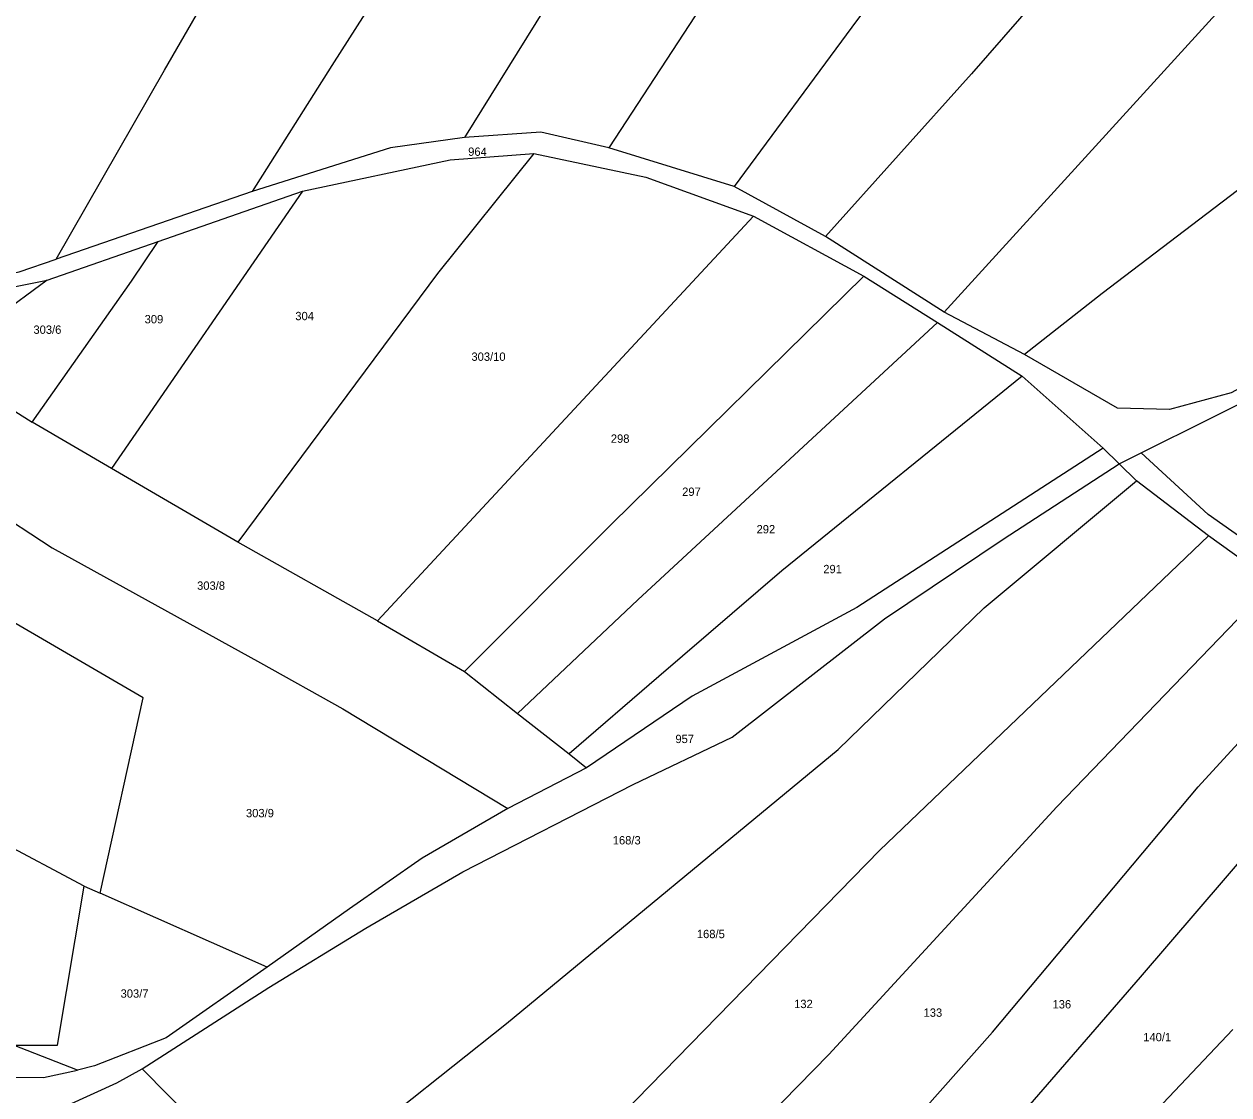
# Model space of a CAD drawing. Extents: x -7483133 to -743907, y -11317770 to -1129777.
# Drawn here: x -747616.9 to -747371.5, y -1130860.3 to -1130642.1 of the extents above; entities that cross this region are included whole.
import ezdxf

# ---------------------------------------------------------------- set-up
doc = ezdxf.new("R2010")
doc.units = 0
doc.layers.add('Hranice parcel', color=7, linetype='Continuous')
doc.layers.add('Parcelní čísla', color=7, linetype='Continuous')

msp = doc.modelspace()

# ---------------------------------------------------------------- linework, layer by layer
at = {"layer": 'Hranice parcel'}
for p, q in [((-747472.3, -1130675.24), (-747497.82, -1130667.33)), ((-747570.47, -1130676.24), (-747610.44, -1130690.04)), ((-747560.26, -1130676.14), (-747599.16, -1130732.71)), ((-747589.6, -1130686.4), (-747560.26, -1130676.14)), ((-747453.65, -1130685.38), (-747472.3, -1130675.24)), ((-747468.33, -1130681.23), (-747544.95, -1130763.72)), ((-747468.33, -1130681.23), (-747445.84, -1130693.47)), ((-747612.23, -1130694.29), (-747589.6, -1130686.4)), ((-747429.5, -1130700.84), (-747453.65, -1130685.38)), ((-747612.23, -1130694.29), (-747634.84, -1130710.99)), ((-747445.84, -1130693.47), (-747430.87, -1130702.94)), ((-747413.11, -1130709.47), (-747429.5, -1130700.84)), ((-747430.87, -1130702.94), (-747413.6, -1130713.86)), ((-747634.84, -1130710.99), (-747615.28, -1130723.21)), ((-747413.6, -1130713.86), (-747397.12, -1130728.52)), ((-747599.16, -1130732.71), (-747615.28, -1130723.21)), ((-747393.87, -1130731.74), (-747397.12, -1130728.52)), ((-747393.87, -1130731.74), (-747389.39, -1130729.51)), ((-747573.4, -1130747.66), (-747599.16, -1130732.71)), ((-747390.31, -1130735.18), (-747393.87, -1130731.74)), ((-747375.64, -1130746.37), (-747390.31, -1130735.18)), ((-747544.95, -1130763.72), (-747573.4, -1130747.66)), ((-747362.47, -1130755.89), (-747375.64, -1130746.37)), ((-747544.95, -1130763.72), (-747527.2, -1130774.05)), ((-747527.2, -1130774.05), (-747516.43, -1130782.61)), ((-747516.43, -1130782.61), (-747505.92, -1130790.81)), ((-747604.68, -1130817.79), (-747653.39, -1130792.09)), ((-747505.92, -1130790.81), (-747502.34, -1130793.69)), ((-747502.34, -1130793.69), (-747518.4, -1130801.96)), ((-747604.68, -1130817.79), (-747601.44, -1130819.19)), ((-747567.45, -1130834.27), (-747601.44, -1130819.19)), ((-747370.72, -1130846.96), (-747398.68, -1130876.61)), ((-747606.08, -1130855.29), (-747619.1, -1130850.16)), ((-747566.95, -1130881.22), (-747592.89, -1130855.02))]:
    msp.add_line(p, q, dxfattribs=at)
for points in [[(-747406.55, -1130442.05), (-747433, -1130473.56), (-747450.34, -1130497.42), (-747482.92, -1130542.77), (-747509.09, -1130578.6), (-747506.37, -1130580.24), (-747519.16, -1130597.89), (-747541.31, -1130630.19), (-747554.26, -1130650.56), (-747570.47, -1130676.24)], [(-747389.81, -1130462.1), (-747422.6, -1130502.65), (-747435.83, -1130522.84), (-747460.61, -1130558.7), (-747496.62, -1130615.91), (-747527.24, -1130665.21)], [(-747372.27, -1130486.53), (-747381.2, -1130496.17), (-747406.45, -1130532.04), (-747427.76, -1130561.72), (-747452.45, -1130598.71), (-747466.25, -1130619), (-747497.82, -1130667.33)], [(-747610.44, -1130690.04), (-747588.32, -1130651.53), (-747569.82, -1130619.41), (-747553.67, -1130593.96), (-747509.74, -1130531.99), (-747495.01, -1130512.09), (-747487.14, -1130500.82)], [(-747347.02, -1130502.76), (-747362.81, -1130523.86), (-747379.15, -1130547.62), (-747394.36, -1130569.03), (-747408.35, -1130589.31), (-747448.34, -1130642.74), (-747472.3, -1130675.24)], [(-747322.61, -1130523.9), (-747334.04, -1130536.83), (-747348.03, -1130555.24), (-747368.31, -1130582.75), (-747365.39, -1130585), (-747397.83, -1130622.33), (-747423.95, -1130652.28), (-747453.65, -1130685.38)], [(-747299.94, -1130546.07), (-747326.43, -1130577.62), (-747348.89, -1130607.4), (-747346.22, -1130610.12), (-747373.45, -1130639.38), (-747429.5, -1130700.84)], [(-747274.92, -1130565.92), (-747285.64, -1130578.76), (-747307.99, -1130610.22), (-747324.13, -1130631.63), (-747321.95, -1130634.31), (-747352.27, -1130662.01), (-747368.33, -1130674.96), (-747397.34, -1130697.03), (-747413.11, -1130709.47)], [(-747527.24, -1130665.21), (-747542.3, -1130667.33), (-747570.47, -1130676.24)], [(-747497.82, -1130667.33), (-747511.65, -1130664.15), (-747527.24, -1130665.21)], [(-747389.39, -1130729.51), (-747347.62, -1130708.71), (-747322.25, -1130690.54), (-747297.3, -1130672.37), (-747285.31, -1130666.64), (-747270.7, -1130664.58), (-747257.03, -1130667.41), (-747246.16, -1130671.52)], [(-747513.08, -1130668.47), (-747532.69, -1130692.96), (-747573.4, -1130747.66)], [(-747560.26, -1130676.14), (-747530.15, -1130669.79), (-747513.08, -1130668.47)], [(-747513.08, -1130668.47), (-747490.25, -1130673.32), (-747468.33, -1130681.23)], [(-747300.62, -1130669.66), (-747353.84, -1130708.05), (-747371.05, -1130717.26), (-747383.63, -1130720.64), (-747394.22, -1130720.39), (-747413.11, -1130709.47)], [(-747615.28, -1130723.21), (-747595.09, -1130694.52), (-747589.6, -1130686.4)], [(-747659.21, -1130698.02), (-747639.49, -1130696.7), (-747617.92, -1130692.58), (-747610.44, -1130690.04)], [(-747650.07, -1130701.82), (-747637.16, -1130699.27), (-747612.23, -1130694.29)], [(-747445.84, -1130693.47), (-747497.27, -1130744), (-747527.2, -1130774.05)], [(-747430.87, -1130702.94), (-747491.91, -1130759.43), (-747516.43, -1130782.61)], [(-747413.6, -1130713.86), (-747462.56, -1130753.54), (-747487.66, -1130775.09), (-747505.92, -1130790.81)], [(-747650.43, -1130722.5), (-747624.13, -1130740.43), (-747611.24, -1130748.86), (-747568.75, -1130772.25), (-747551.99, -1130781.63), (-747518.4, -1130801.96)], [(-747397.12, -1130728.52), (-747447.29, -1130761.01), (-747480.85, -1130779.08), (-747502.34, -1130793.69)], [(-747344.46, -1130764.04), (-747375.72, -1130742.04), (-747389.39, -1130729.51)], [(-747592.89, -1130855.02), (-747567.07, -1130838.41), (-747547.35, -1130826.32), (-747527.53, -1130814.88), (-747492.89, -1130797.06), (-747472.69, -1130787.42), (-747441.69, -1130763.28), (-747417.46, -1130747.1), (-747393.87, -1130731.74)], [(-747566.95, -1130881.22), (-747540.53, -1130863.15), (-747518.65, -1130845.8), (-747451.1, -1130789.94), (-747421.34, -1130761.04), (-747390.31, -1130735.18)], [(-747601.44, -1130819.19), (-747592.67, -1130779.43), (-747629.73, -1130757.9), (-747657.09, -1130741.32)], [(-747375.64, -1130746.37), (-747442.58, -1130810.47), (-747503.21, -1130872.55), (-747525.65, -1130895.32), (-747538.78, -1130907.97)], [(-747516.82, -1130918.2), (-747509.43, -1130909.76), (-747453.02, -1130852.06), (-747406.54, -1130801.59), (-747362.47, -1130755.89)], [(-747464.43, -1130898), (-747419.65, -1130847.56), (-747377.79, -1130797.57), (-747349.46, -1130766.63)], [(-747452.04, -1130908.53), (-747389.53, -1130836.33), (-747337.16, -1130775.31)], [(-747518.4, -1130801.96), (-747535.86, -1130812.1), (-747550.62, -1130822.39), (-747567.45, -1130834.27)], [(-747619.1, -1130850.16), (-747610.15, -1130850.19), (-747604.68, -1130817.79)], [(-747567.45, -1130834.27), (-747588.01, -1130848.67), (-747602.62, -1130854.39), (-747606.08, -1130855.29)], [(-747663.88, -1130851.09), (-747634.6, -1130856.66), (-747613, -1130856.77), (-747606.08, -1130855.29)], [(-747613.42, -1130864.85), (-747598.03, -1130857.85), (-747592.89, -1130855.02)]]:
    msp.add_lwpolyline(points, dxfattribs=at)

# ---------------------------------------------------------------- texts
at = {"layer": 'Parcelní čísla'}
for s, p in [('964', (-747526.47, -1130668.97)), ('309', (-747592.39, -1130703.1)), ('304', (-747561.69, -1130702.46)), ('303/6', (-747615.04, -1130705.24)), ('303/10', (-747525.81, -1130710.74)), ('298', (-747497.41, -1130727.44)), ('297', (-747482.88, -1130738.26)), ('292', (-747467.72, -1130745.9)), ('291', (-747454.13, -1130754.02)), ('303/8', (-747581.7, -1130757.39)), ('957', (-747484.26, -1130788.63)), ('303/9', (-747571.74, -1130803.75)), ('168/3', (-747497.02, -1130809.28)), ('168/5', (-747479.88, -1130828.38)), ('303/7', (-747597.29, -1130840.51)), ('132', (-747460.07, -1130842.63)), ('136', (-747407.43, -1130842.7)), ('133', (-747433.7, -1130844.4)), ('140/1', (-747388.94, -1130849.39))]:
    msp.add_text(s, height=1.7, dxfattribs=at).set_placement(p)

doc.saveas('drawing.dxf')
